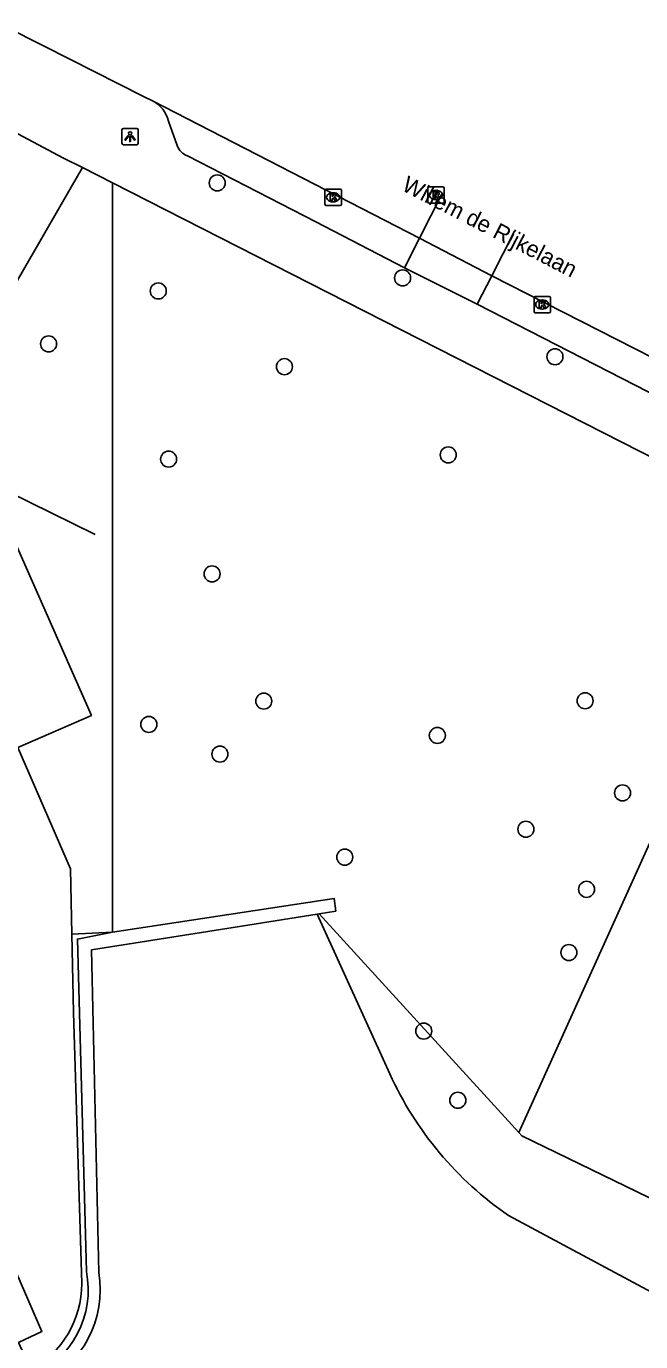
# Model space of a CAD drawing. Extents: x 159503 to 160347, y 382525 to 383272.
# Drawn here: x 160251 to 160288.6, y 382870.4 to 382950.8 of the extents above; entities that cross this region are included whole.
import ezdxf

# ---------------------------------------------------------------- set-up
doc = ezdxf.new("R2010")
doc.units = 0
for name, color, linetype in [('IMGEO_Boom', 7, 'Continuous'), ('IMGEO_Groenvoorziening', 7, 'Continuous'), ('IMGEO_Hek', 7, 'Continuous'), ('IMGEO_Kademuur', 7, 'Continuous'), ('IMGEO_Kolk', 7, 'Continuous'), ('IMGEO_Lichtpunt', 7, 'Continuous'), ('IMGEO_Loofbos', 7, 'Continuous'), ('IMGEO_Meer_plas_ven_vijver', 7, 'Continuous'), ('IMGEO_Openbare_ruimte_label', 7, 'Continuous'), ('IMGEO_Parkeervlak_open', 7, 'Continuous'), ('IMGEO_Rijbaan_lokaal_open', 7, 'Continuous'), ('IMGEO_Rioolput', 7, 'Continuous'), ('IMGEO_Voetpad_open', 7, 'Continuous')]:
    doc.layers.add(name, color=color, linetype=linetype)

msp = doc.modelspace()

# ---------------------------------------------------------------- linework, layer by layer
at = {"layer": 'IMGEO_Boom'}
for centre in [(160262.707, 382941.202), (160274.028, 382935.398), (160259.108, 382934.601), (160252.411, 382931.372), (160283.331, 382930.584), (160266.811, 382929.979), (160276.812, 382924.593), (160259.74, 382924.331), (160262.391, 382917.323), (160265.549, 382909.552), (160285.172, 382909.573), (160258.53, 382908.132), (160276.147, 382907.455), (160262.87, 382906.316), (160287.456, 382903.949), (160281.553, 382901.728), (160270.493, 382900.023), (160285.258, 382898.059), (160284.178, 382894.2), (160275.317, 382889.403), (160277.398, 382885.175)]:
    msp.add_circle(centre, 0.489, dxfattribs=at)
at = {"layer": 'IMGEO_Groenvoorziening'}
msp.add_lwpolyline([(160301.714, 382873.091), (160281.3, 382883.01), (160281.12, 382883.208)], dxfattribs=at)
at = {"layer": 'IMGEO_Hek'}
for points in [[(160256.314, 382895.445), (160256.305, 382941.201)], [(160244.569, 382924.981), (160255.243, 382919.736)], [(160253.833, 382895.313), (160256.314, 382895.445)]]:
    msp.add_lwpolyline(points, dxfattribs=at)
at = {"layer": 'IMGEO_Kademuur'}
for points in [[(160256.314, 382895.445), (160269.837, 382897.506), (160269.947, 382896.726), (160268.939, 382896.566)], [(160268.799, 382896.544), (160263.291, 382895.671), (160255.021, 382894.36), (160255.474, 382874.651)], [(160268.939, 382896.566), (160268.799, 382896.544)], [(160256.314, 382895.445), (160254.169, 382895.018), (160254.714, 382874.72)]]:
    msp.add_lwpolyline(points, dxfattribs=at)
for centre, radius, start, end in [((160249.067, 382873.586), 5.759, 293.72894, 11.35205), ((160249.214, 382873.589), 6.35, 294.78854, 9.63075)]:
    msp.add_arc(centre, radius, start, end, dxfattribs=at)
at = {"layer": 'IMGEO_Kolk'}
for p, q in [((160269.285, 382939.899), (160269.285, 382940.751)), ((160269.36, 382940.825), (160270.212, 382940.825)), ((160269.773, 382940.605), (160269.798, 382940.605)), ((160270.286, 382940.751), (160270.286, 382939.899)), ((160270.212, 382939.825), (160269.36, 382939.825)), ((160269.796, 382940.045), (160269.771, 382940.045)), ((160282.052, 382933.348), (160282.052, 382934.2)), ((160282.127, 382934.274), (160282.979, 382934.274)), ((160282.54, 382934.054), (160282.565, 382934.054)), ((160283.053, 382934.2), (160283.053, 382933.348)), ((160282.979, 382933.274), (160282.127, 382933.274)), ((160282.563, 382933.494), (160282.538, 382933.494))]:
    msp.add_line(p, q, dxfattribs=at)
for points in [[(160269.285, 382939.899), (160269.285, 382940.751)], [(160269.36, 382940.825), (160270.212, 382940.825)], [(160269.606, 382940.525), (160269.729, 382940.525), (160269.729, 382940.374), (160269.859, 382940.525), (160270.023, 382940.525), (160269.877, 382940.374), (160270.03, 382940.125), (160269.878, 382940.125), (160269.793, 382940.289), (160269.729, 382940.222), (160269.729, 382940.125), (160269.606, 382940.125), (160269.606, 382940.525)], [(160270.286, 382940.751), (160270.286, 382939.899)], [(160270.212, 382939.825), (160269.36, 382939.825)], [(160282.052, 382933.348), (160282.052, 382934.2)], [(160282.127, 382934.274), (160282.979, 382934.274)], [(160282.373, 382933.974), (160282.496, 382933.974), (160282.496, 382933.823), (160282.626, 382933.974), (160282.79, 382933.974), (160282.644, 382933.823), (160282.797, 382933.574), (160282.645, 382933.574), (160282.56, 382933.738), (160282.496, 382933.671), (160282.496, 382933.574), (160282.373, 382933.574), (160282.373, 382933.974)], [(160283.053, 382934.2), (160283.053, 382933.348)], [(160282.979, 382933.274), (160282.127, 382933.274)]]:
    msp.add_lwpolyline(points, dxfattribs=at)
for centre, start, end in [((160269.362, 382940.749), 91.55205, 178.44795), ((160269.362, 382940.749), 91.55205, 178.44795), ((160270.21, 382940.749), 1.55205, 88.44795), ((160270.21, 382940.749), 1.55205, 88.44795), ((160269.362, 382939.901), 181.55205, 268.44795), ((160269.362, 382939.901), 181.55205, 268.44795), ((160270.21, 382939.901), 271.55205, 358.44795), ((160270.21, 382939.901), 271.55205, 358.44795), ((160282.129, 382934.198), 91.55205, 178.44795), ((160282.129, 382934.198), 91.55205, 178.44795), ((160282.977, 382934.198), 1.55205, 88.44795), ((160282.977, 382934.198), 1.55205, 88.44795), ((160282.129, 382933.35), 181.55205, 268.44795), ((160282.129, 382933.35), 181.55205, 268.44795), ((160282.977, 382933.35), 271.55205, 358.44795), ((160282.977, 382933.35), 271.55205, 358.44795)]:
    msp.add_arc(centre, 0.0765, start, end, dxfattribs=at)
for centre, major_axis, ratio, start_param, end_param in [((160269.772, 382940.325), (-0.387, 0.002), 0.722429, 4.712389, 7.853982), ((160269.797, 382940.325), (-0.39, 0.002), 0.717154, 1.570796, 4.712389), ((160282.539, 382933.774), (-0.387, 0.002), 0.722429, 4.712389, 7.853982), ((160282.564, 382933.774), (-0.39, 0.002), 0.717154, 1.570796, 4.712389)]:
    msp.add_ellipse(centre, major_axis=major_axis, ratio=ratio, start_param=start_param, end_param=end_param, dxfattribs=at)
at = {"layer": 'IMGEO_Lichtpunt'}
for p, q in [((160256.887, 382944.434), (160256.887, 382943.627)), ((160256.887, 382944.434), (160256.887, 382943.627)), ((160257.789, 382944.529), (160256.981, 382944.529)), ((160257.789, 382944.529), (160256.981, 382944.529)), ((160257.883, 382943.627), (160257.883, 382944.434)), ((160257.883, 382943.627), (160257.883, 382944.434)), ((160256.981, 382943.533), (160257.789, 382943.533)), ((160256.981, 382943.533), (160257.789, 382943.533))]:
    msp.add_line(p, q, dxfattribs=at)
for points in [[(160257.261, 382944.098), (160257.3, 382944.07), (160257.112, 382943.808), (160257.074, 382943.835), (160257.261, 382944.098)], [(160257.363, 382944.05), (160257.41, 382944.05), (160257.41, 382943.728), (160257.363, 382943.728), (160257.363, 382944.05)], [(160257.473, 382944.07), (160257.511, 382944.097), (160257.698, 382943.835), (160257.659, 382943.807), (160257.473, 382944.07)]]:
    msp.add_lwpolyline(points, dxfattribs=at)
msp.add_circle((160257.386, 382944.232), 0.0994, dxfattribs=at)
for centre, start, end in [((160256.981, 382944.434), 90, 180), ((160256.981, 382944.434), 90, 180), ((160257.789, 382944.434), 0, 90), ((160257.789, 382944.434), 0, 90), ((160256.981, 382943.627), 180, 270), ((160256.981, 382943.627), 180, 270), ((160257.789, 382943.627), 270, 0), ((160257.789, 382943.627), 270, 360)]:
    msp.add_arc(centre, 0.0946, start, end, dxfattribs=at)
at = {"layer": 'IMGEO_Loofbos'}
for points in [[(160256.305, 382941.201), (160256.314, 382895.445)], [(160297.798, 382920.081), (160281.12, 382883.208)], [(160281.12, 382883.208), (160268.939, 382896.566)]]:
    msp.add_lwpolyline(points, dxfattribs=at)
at = {"layer": 'IMGEO_Meer_plas_ven_vijver'}
for points in [[(160273.247, 382886.798), (160268.799, 382896.544)], [(160294.885, 382870.432), (160280.495, 382878.142)]]:
    msp.add_lwpolyline(points, dxfattribs=at)
msp.add_arc((160292.339, 382895.422), 20.95, 204.30919, 235.57226, dxfattribs=at)
at = {"layer": 'IMGEO_Parkeervlak_open'}
for points in [[(160274.138, 382936.023), (160275.054, 382937.818)], [(160279.467, 382935.529), (160278.588, 382933.799)], [(160244.184, 382920.931), (160248.718, 382922.931), (160255.026, 382908.685), (160250.528, 382906.724)], [(160256.314, 382895.445), (160253.833, 382895.313)]]:
    msp.add_lwpolyline(points, dxfattribs=at)
at = {"layer": 'IMGEO_Rijbaan_lokaal_open'}
for points in [[(160258.758, 382946.215), (160258.207, 382946.477), (160252.169, 382949.542), (160249.725, 382950.766)], [(160258.758, 382946.215), (160275.054, 382937.818)], [(160250.523, 382944.193), (160253.329, 382942.715), (160254.472, 382942.133)], [(160244.569, 382924.981), (160244.613, 382925.056), (160244.657, 382925.13), (160254.472, 382942.133)], [(160276.427, 382940.509), (160275.054, 382937.818)], [(160275.054, 382937.818), (160279.467, 382935.529)], [(160280.85, 382938.25), (160279.467, 382935.529)], [(160279.467, 382935.529), (160300.207, 382924.953)], [(160250.528, 382906.724), (160253.748, 382899.309), (160253.833, 382895.313)], [(160253.833, 382895.313), (160253.934, 382890.538), (160254.441, 382873.98)], [(160251.337, 382868.693), (160250.579, 382870.382), (160252, 382871.063), (160250.136, 382875.329)]]:
    msp.add_lwpolyline(points, dxfattribs=at)
msp.add_arc((160248.33, 382874.013), 6.111, 299.47331, 359.69226, dxfattribs=at)
at = {"layer": 'IMGEO_Rioolput'}
for p, q in [((160275.638, 382940.96), (160276.49, 382940.96)), ((160275.563, 382940.034), (160275.563, 382940.886)), ((160276.074, 382940.18), (160276.049, 382940.18)), ((160276.051, 382940.74), (160276.076, 382940.74)), ((160276.564, 382940.886), (160276.564, 382940.034)), ((160276.49, 382939.96), (160275.638, 382939.96))]:
    msp.add_line(p, q, dxfattribs=at)
for points in [[(160275.638, 382940.96), (160276.49, 382940.96)], [(160275.563, 382940.034), (160275.563, 382940.886)], [(160276.152, 382940.658), (160275.9, 382940.66), (160275.9, 382940.26)], [(160275.9, 382940.26), (160276.024, 382940.26), (160276.024, 382940.422), (160276.035, 382940.422)], [(160276.078, 382940.579), (160276.024, 382940.579), (160276.024, 382940.498)], [(160276.024, 382940.498), (160276.076, 382940.498)], [(160276.082, 382940.393), (160276.153, 382940.26), (160276.293, 382940.26), (160276.228, 382940.386)], [(160276.564, 382940.886), (160276.564, 382940.034)], [(160276.49, 382939.96), (160275.638, 382939.96)]]:
    msp.add_lwpolyline(points, dxfattribs=at)
for centre, radius, start, end in [((160275.64, 382940.884), 0.0765, 91.55205, 178.44795), ((160275.64, 382940.884), 0.0765, 91.55205, 178.44795), ((160276.488, 382940.884), 0.0765, 1.55205, 88.44795), ((160276.488, 382940.884), 0.0765, 1.55205, 88.44795), ((160276.034, 382940.369), 0.0533, 26.02933, 88.69889), ((160276.06, 382940.687), 0.19, 274.7715, 282.96867), ((160276.084, 382940.483), 0.0964, 77.00612, 93.18647), ((160276.098, 382940.54), 0.0378, 276.66336, 79.67722), ((160276.151, 382940.548), 0.109, 350.36119, 89.41601), ((160276.149, 382940.548), 0.112, 277.58423, 350.98172), ((160276.133, 382940.333), 0.108, 29.51342, 73.79051), ((160275.64, 382940.036), 0.0765, 181.55205, 268.44795), ((160275.64, 382940.036), 0.0765, 181.55205, 268.44795), ((160276.488, 382940.036), 0.0765, 271.55205, 358.44795), ((160276.488, 382940.036), 0.0765, 271.55205, 358.44795)]:
    msp.add_arc(centre, radius, start, end, dxfattribs=at)
for centre, major_axis, ratio, start_param, end_param in [((160276.05, 382940.46), (-0.387, 0.002), 0.722429, 4.712389, 7.853982), ((160276.075, 382940.46), (-0.39, 0.002), 0.717154, 1.570796, 4.712389)]:
    msp.add_ellipse(centre, major_axis=major_axis, ratio=ratio, start_param=start_param, end_param=end_param, dxfattribs=at)
at = {"layer": 'IMGEO_Voetpad_open'}
for points in [[(160260.265, 382943.483), (160259.73, 382944.977)], [(160274.138, 382936.023), (160268.725, 382938.815), (160260.886, 382942.859)], [(160254.472, 382942.133), (160256.305, 382941.201)], [(160256.305, 382941.201), (160267.269, 382935.624), (160290.738, 382923.687), (160293.682, 382922.189), (160297.798, 382920.081)], [(160278.588, 382933.799), (160274.138, 382936.023)], [(160296.253, 382924.736), (160278.588, 382933.799)]]:
    msp.add_lwpolyline(points, dxfattribs=at)
for centre, radius, start, end in [((160257.848, 382944.5), 1.942, 14.22555, 62.04801), ((160261.192, 382943.785), 0.975, 198.02711, 251.69676)]:
    msp.add_arc(centre, radius, start, end, dxfattribs=at)

# ---------------------------------------------------------------- texts
at = {"layer": 'IMGEO_Openbare_ruimte_label'}
msp.add_text('Willem de Rijkelaan', height=1, rotation=332.69222, dxfattribs=at).set_placement((160273.909, 382940.779))

doc.saveas('drawing.dxf')
